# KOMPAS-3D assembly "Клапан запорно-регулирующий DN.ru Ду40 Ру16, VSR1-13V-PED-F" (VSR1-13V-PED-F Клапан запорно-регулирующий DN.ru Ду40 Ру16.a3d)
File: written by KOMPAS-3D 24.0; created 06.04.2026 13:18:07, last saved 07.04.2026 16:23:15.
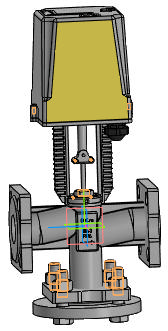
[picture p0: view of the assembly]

Document properties: Автор: R2D2; Полное имя файла: E:\Работа\Зайцев\Солянка\VSR1-13V-PED-F Клапан запорно-регулирующий DN.ru\DN40\исходные материалы\VSR1-13V-PED-F Клапан запорно-регулирующий DN.ru Ду32 Ру16.a3d

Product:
- Component [detail]: Фланец  | qty 2  | pos. 1  | Масса: 1.237185; Автор: R2D2; source file: Фланец.m3d
- Component [detail]: Фланец  | qty 1  | pos. 2  | Масса: 1.237185; Автор: R2D2; source file: Фланец.m3d
- Component [detail]: Корпус  | qty 1  | pos. 3  | Масса: 6.9; Автор: R2D2; source file: Корпус.m3d
- Component [detail]: Электропривод  | qty 1  | pos. 6  | Масса: 0.101125; Автор: R2D2; source file: Электропривод.m3d
- Component [standard]: Болт с шестигранной головкой ГОСТ Р ИСО 4014 - М16 x 65  | qty 4  | pos. 7  | Материал: Не определено (density 1000 kg/m3); Масса: 0.1404; Раздел спецификации: Стандартные изделия; Рассекать на разрезах: no; additional columns: ГОСТ Р ИСО 4014-2013
- Component [standard]: Гайка М16-6H ГОСТ 5915-70  | qty 4  | pos. 8  | Масса: 0.03761; Раздел спецификации: Стандартные изделия; Рассекать на разрезах: no; additional columns: М1,6-6H
- Part/product: Клапан запорно-регулирующий DN.ru Ду40 Ру16  | designation VSR1-13V-PED-F
    Масса: 10.5
    Раздел спецификации: Прочие изделия
    Примечание: D090-02890

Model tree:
1. Эскиз:1
2. Ось конической поверхности:19
3. Смещенная плоскость:19
4. ЛСК:19  (with: Плоскость XY, Плоскость ZX, Плоскость ZY, Ось X, Ось Y, Ось Z)
     Ось X. Y = -1; Ось Y. X = 1; Ось Z. Z = 1; Точка начала. Х = 38.8909; Точка начала. Y = -120; Точка начала. Z = 38.8909
5. Болтовое соединение
6. Массив по концентрической сетке:3  (with: Грань.Элемент выдавливания:1, Грань.Элемент вращения:1, Грань.Элемент выдавливания:8)  (4 pattern instances)
     Шаг 2 = 360; Ориентация = 2; Расстояние = -2; Расстояние = -36

Expressions: VSR1-13V-PED-F; -L/2
Referenced files in E:\Работа\Зайцев\Солянка\VSR1-13V-PED-F Клапан запорно-регулирующий DN.ru\DN40\исходные материалы\: Фланец.m3d, Корпус.m3d, Электропривод.m3d
Referenced files in C:\Program Files\ASCON\KOMPAS-3D v24\Libs\PolynomLib\DATA\vault\Methods\Kompas\3D\: PLib_Bolt_1_ISO_1100.m3d, PLib_Nut_OST92_900.m3d
Referenced files in E:\Работа\Зайцев\Солянка\VSR1-13V-PED-F Клапан запорно-регулирующий DN.ru\DN20\исходные материалы\: Фланец.m3d
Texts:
  Болт с шестигранной головкой
  Крепежное изделие ГОСТ
  Программные изделия  и базы данных
  Edge1
  Edge2
  TKR3D
  Справочник стандартных изделий
  Фланец (1)
  Фланец (2)
  Фланец (3)
  Болт с шестигранной головкой ГОСТ Р ИСО 4014 - М16 x 65 (1)
  hole1
  hole2
  bcut1
  hcut1
  cut1
  Плоскость XY.Начало координат
  Ось Z.Начало координат
  Плоскость ZY.Начало координат
  Плоскость ZX.Начало координат
  Ось Y.Начало координат
  Plane. Начало координат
